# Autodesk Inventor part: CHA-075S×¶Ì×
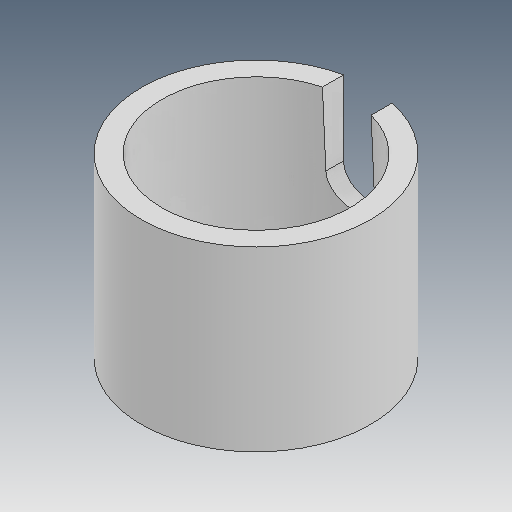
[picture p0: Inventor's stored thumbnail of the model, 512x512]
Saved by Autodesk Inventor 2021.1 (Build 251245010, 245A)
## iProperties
Created: 2019-05
Part Number: CHA-075S×¶Ì×
Material: Ogólny
Document SubType Name: Modeling
Designer: user
Density: 1 g/cm^3
Appearance: Domyślna
Author: user
Revision Number: ÈÎºÎ
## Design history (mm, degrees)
feature "ÊäÈë1"
node "Bryła1"
